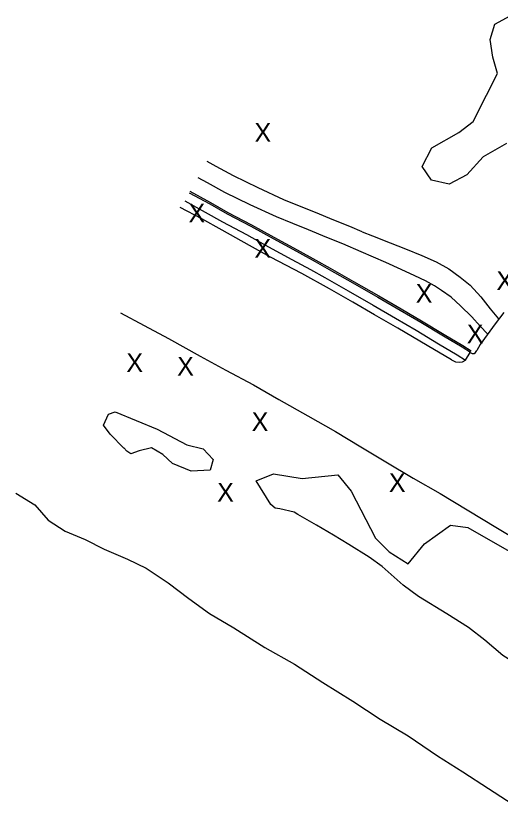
# Model space of a CAD drawing. Extents: x 2023750 to 2025732, y 819696 to 821148.
# Drawn here: x 2023749.6 to 2024009.1, y 820723.4 to 821148.1 of the extents above; entities that cross this region are included whole.
import ezdxf

# ---------------------------------------------------------------- set-up
doc = ezdxf.new("R2010")
doc.units = 0
for name, color, linetype in [('Old_Level_11', 7, 'Continuous'), ('Old_Level_3', 7, 'Continuous'), ('Old_Level_8', 7, 'Continuous')]:
    doc.layers.add(name, color=color, linetype=linetype)

msp = doc.modelspace()

# ---------------------------------------------------------------- linework, layer by layer
at = {"layer": 'Old_Level_11'}
for points in [[(2024012.52, 821079.55), (2023999.98, 821072.47), (2023991.19, 821062.77), (2023981.81, 821057.92), (2023972.34, 821060.05), (2023967.32, 821067.32), (2023972.45, 821077.34), (2023986.98, 821085.48), (2023994.63, 821091.41), (2024001.78, 821105.61), (2024007.63, 821117.1), (2024005.18, 821125.97), (2024003.69, 821135.3), (2024006.26, 821143.64), (2024014.37, 821148.05)], [(2023807.43, 820916.32), (2023800.11, 820923.83), (2023796.51, 820928.72), (2023799.25, 820934.61), (2023802.83, 820935.79), (2023825.3, 820926.47), (2023841.15, 820918.08), (2023849.94, 820916.08), (2023855.26, 820910.23), (2023853.61, 820904.49), (2023843.44, 820904.04), (2023833.53, 820908.19), (2023828.4, 820913.04), (2023822.21, 820916.6), (2023815.58, 820914.92), (2023811.11, 820913.27), (2023809.03, 820914.7), (2023807.51, 820916.48)], [(2023886.16, 820886.12), (2023878.35, 820898.89), (2023878.35, 820898.89), (2023887.64, 820902.52), (2023903.04, 820900.1), (2023922.01, 820902.04), (2023929.17, 820893.3), (2023942.31, 820868.19), (2023949.68, 820860.87), (2023959.71, 820854.36), (2023968.53, 820865.07), (2023982.43, 820875.07), (2023991.72, 820873.8), (2024025.1, 820854.78), (2024027.46, 820845.38), (2024020.57, 820831.53), (2024018.12, 820823.89), (2024023.71, 820818.43), (2024047.88, 820805.79), (2024075.43, 820785.98), (2024099.53, 820766.28), (2024118.22, 820752.93)], [(2023749.58, 820892.2), (2023759.7, 820886.01), (2023766.97, 820877.8), (2023776.07, 820871.86), (2023786.73, 820867.36), (2023796.97, 820862.24), (2023809.35, 820856.95), (2023819.46, 820851.99), (2023831.19, 820844.2), (2023842.23, 820835.74), (2023853.25, 820827.76), (2023866.31, 820820.15), (2023883, 820809.54), (2023898.91, 820800.65), (2023914.02, 820790.78), (2023930.11, 820780.68), (2023944.85, 820771.1), (2023959.78, 820762.16), (2023975.51, 820751.38), (2023989.03, 820742.91), (2024002.83, 820733.88), (2024019.06, 820723.43)], [(2024107.02, 820738.73), (2024096.09, 820744.78), (2024082.45, 820755.07), (2024069.06, 820764.85), (2024056.73, 820774.58), (2024046.56, 820781.21), (2024033.7, 820791.38), (2024022.86, 820797.53), (2024010.47, 820805.25), (2024000.84, 820813.49), (2023992.04, 820820.2), (2023980.53, 820827.57), (2023965.36, 820836.87), (2023957.03, 820843), (2023945.88, 820852.87), (2023938.79, 820857.9), (2023928.07, 820864.71), (2023919.76, 820869.73), (2023910.71, 820875.08), (2023900.57, 820880.81), (2023898.64, 820881.99), (2023890.98, 820883.78), (2023888.59, 820884.24), (2023886.16, 820886.12)]]:
    msp.add_lwpolyline(points, dxfattribs=at)
at = {"layer": 'Old_Level_3'}
for points in [[(2023935.06, 821032.35), (2023928.59, 821035.18), (2023919.95, 821038.52), (2023910.21, 821042.64), (2023901.63, 821046.04), (2023893.18, 821049.49), (2023879.48, 821055.86), (2023866.17, 821062.34), (2023856.99, 821067.35), (2023852.11, 821069.99)], [(2023987.89, 820992.67), (2023982.74, 820997.21), (2023977.64, 821000.86), (2023973.96, 821003.29), (2023969.07, 821006.04), (2023963.38, 821008.8), (2023956.08, 821012.17), (2023947.89, 821015.87), (2023934.66, 821021.6), (2023924.78, 821025.92), (2023916.19, 821029.24), (2023906.41, 821033.38), (2023897.9, 821036.75), (2023889.17, 821040.32), (2023875.18, 821046.82), (2023861.57, 821053.44), (2023852.21, 821058.55), (2023847.35, 821061.18)], [(2023842.46, 821053.28), (2023853.46, 821047.22), (2023862.76, 821041.97), (2023875.42, 821035.25), (2023887.41, 821028.68), (2023899.86, 821021.9), (2023909.86, 821016.38), (2023917.52, 821012.15), (2023930.04, 821004.97), (2023943.54, 820997.3), (2023955.52, 820990.3), (2023966.53, 820983.81), (2023978.64, 820976.51), (2023988.64, 820970.61), (2023993.14, 820967.8)], [(2023840.06, 821048.94), (2023851.05, 821042.88), (2023860.38, 821037.62), (2023873.07, 821030.88), (2023885.03, 821024.33), (2023897.47, 821017.55), (2023907.47, 821012.03), (2023915.09, 821007.83), (2023927.58, 821000.67), (2023941.06, 820993.01), (2023953.01, 820986.02), (2023963.99, 820979.55), (2023976.1, 820972.25), (2023986.06, 820966.37), (2023990.51, 820963.59)], [(2023982.9, 820963.61), (2023970.02, 820971.36), (2023954.17, 820980.62), (2023941.81, 820987.9), (2023930.19, 820994.67), (2023917.66, 821001.73), (2023902.72, 821009.91), (2023886.02, 821018.77), (2023874.78, 821025), (2023860.15, 821033.19), (2023849.28, 821039.19), (2023837.62, 821045.34)], [(2023935.06, 821032.35), (2023940.74, 821030.2), (2023950.15, 821026.46), (2023958.41, 821023.14), (2023967.16, 821019.56), (2023974.8, 821016.15), (2023981.58, 821012.43), (2023987.7, 821007.98), (2023993.05, 821003.63), (2023998.74, 820997.4), (2024003.78, 820991.1)], [(2024002.35, 820977.55), (2023998.41, 820981.79), (2023993.94, 820986.66), (2023987.89, 820992.67)], [(2024003.78, 820991.1), (2024008.17, 820985.75)], [(2023805.72, 820988.93), (2023818.39, 820982.15), (2023831.36, 820975.11), (2023848.38, 820965.73), (2023862.12, 820958.11), (2023876.83, 820950.33), (2023890.52, 820942.43), (2023906.1, 820933.75), (2023920.81, 820925.24), (2023934.42, 820917.09), (2023947.89, 820908.97), (2023962.46, 820900.34), (2023976.94, 820892.01), (2024006.81, 820874.03), (2024022.39, 820864.6)], [(2024010.98, 820989.03), (2024006.31, 820983.08), (2024002.09, 820977.04), (2023998.39, 820971.98), (2023996.55, 820968.74)], [(2023982.9, 820963.61), (2023985.12, 820962.71), (2023987.1, 820962.42), (2023988.88, 820962.61), (2023990.51, 820963.59), (2023993.06, 820967.58)], [(2023993.06, 820967.58), (2023994.12, 820967.07), (2023995.09, 820967.09), (2023995.92, 820967.63), (2023996.55, 820968.74)]]:
    msp.add_lwpolyline(points, dxfattribs=at)
at = {"layer": 'Old_Level_8'}
msp.add_lwpolyline([(2023842.87, 821054.03), (2023853.88, 821047.96), (2023863.17, 821042.72), (2023875.83, 821036), (2023887.82, 821029.43), (2023900.27, 821022.65), (2023910.28, 821017.12), (2023917.94, 821012.9), (2023930.46, 821005.72), (2023943.97, 820998.05), (2023955.95, 820991.03), (2023966.97, 820984.55), (2023979.08, 820977.24), (2023989.08, 820971.35), (2023993.6, 820968.52)], dxfattribs=at)

# ---------------------------------------------------------------- texts
at = {"layer": 'Old_Level_11'}
for p in [(2023877.46, 821080.54), (2023842.06, 821037.34), (2023877.4, 821018.44), (2024007.08, 821001.15), (2023963.84, 820994.34), (2023991.2, 820972.62), (2023808.8, 820957.2), (2023836.01, 820955.3), (2023875.93, 820925.56), (2023949.46, 820892.89), (2023857.44, 820887.74)]:
    msp.add_text('X', height=10, dxfattribs=at).set_placement(p)

doc.saveas('drawing.dxf')
